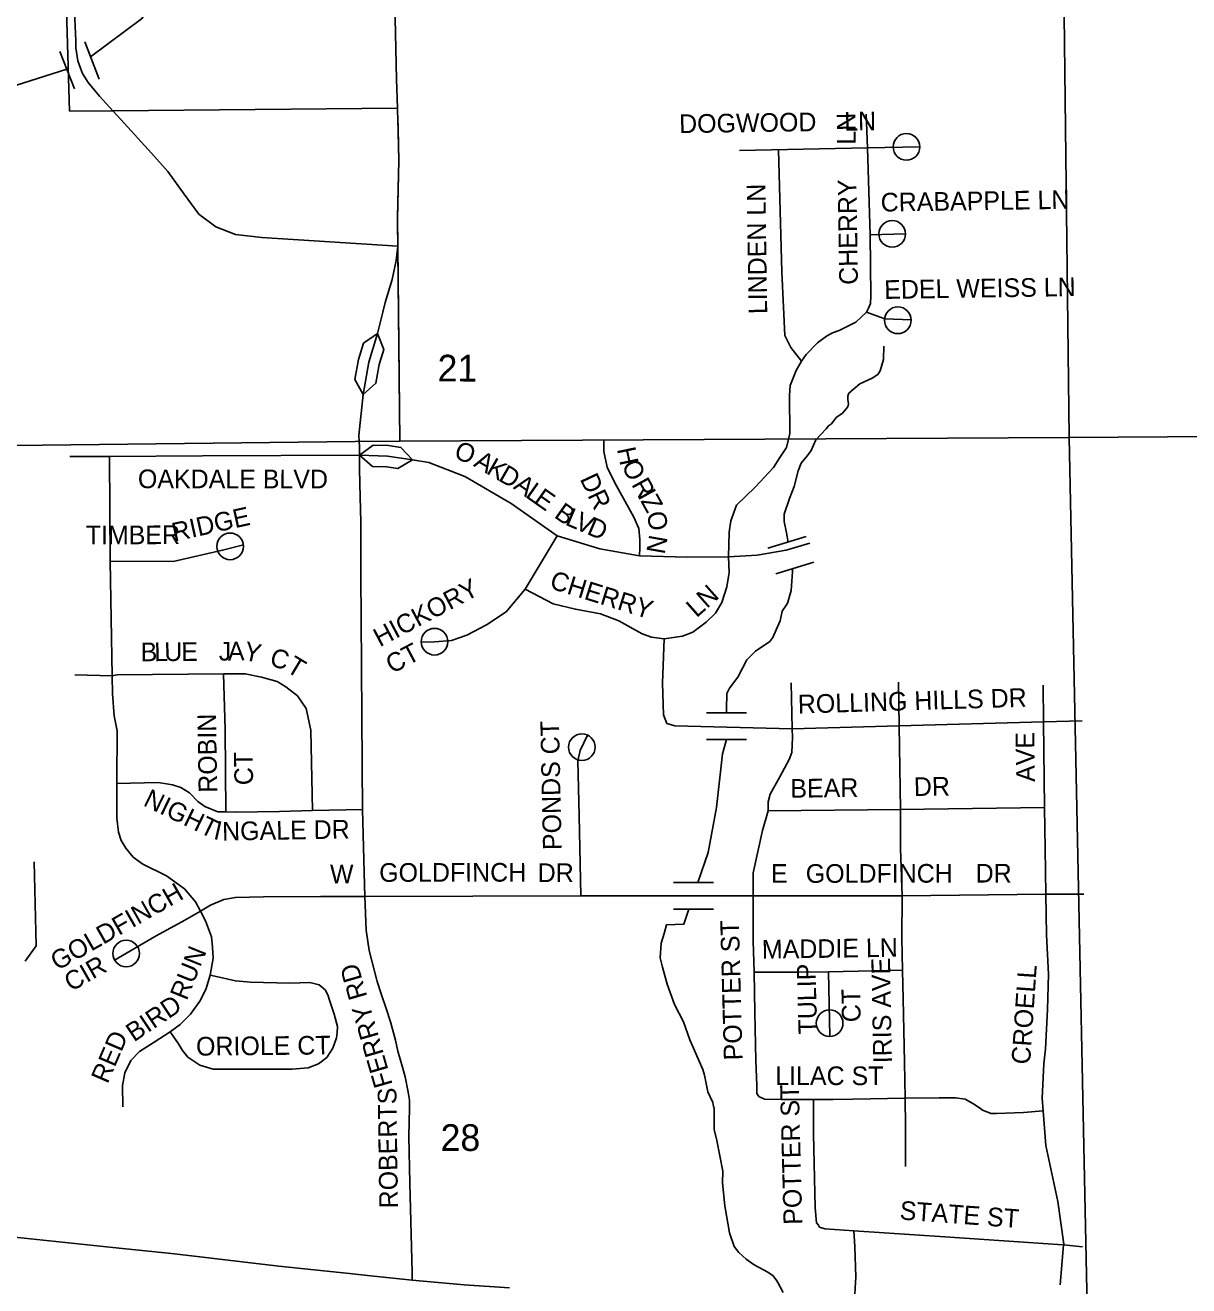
# Model space of a CAD drawing. Extents: x 281.94 to 289.14, y 116.09 to 120.89.
# Drawn here: x 283.875 to 284.748, y 118.797 to 119.742 of the extents above; entities that cross this region are included whole.
import ezdxf

# ---------------------------------------------------------------- set-up
doc = ezdxf.new("R2010")
doc.units = 0
for name, color, linetype in [('tdCiCityCuldesac', 7, 'Continuous'), ('tdCiCityDivCarto', 7, 'Continuous'), ('tdCiCityDivCL', 7, 'Continuous'), ('tdCiCityStreetCL', 7, 'Continuous'), ('tdCiCityStreetTxt', 7, 'Continuous'), ('tdCiCorpBndry', 7, 'Continuous'), ('tdCiCorpBndryPart', 7, 'Continuous'), ('tdCiHydroRiver', 7, 'Continuous'), ('tdCiPriCL', 7, 'Continuous'), ('tdCiPriDiv', 7, 'Continuous'), ('tdCiSecCL', 7, 'Continuous'), ('tdCiSecDivCL', 7, 'Continuous'), ('tdCiSectLine', 7, 'Continuous'), ('tdCiSectNmbr', 7, 'Continuous'), ('tdCiStrucCartoClvrt', 7, 'Continuous')]:
    doc.layers.add(name, color=color, linetype=linetype)

msp = doc.modelspace()

# ---------------------------------------------------------------- linework, layer by layer
at = {"layer": 'tdCiCityCuldesac'}
for centre in [(284.53592, 119.65052), (284.52524, 119.58531), (284.52947, 119.52057), (284.0288, 119.35111), (284.18207, 119.27963), (284.29256, 119.20057), (283.95083, 119.04592), (284.47832, 118.99364)]:
    msp.add_circle(centre, 0.01, dxfattribs=at)
at = {"layer": 'tdCiCityDivCarto'}
for points in [[(284.12858, 119.46491), (284.12241, 119.47613), (284.125, 119.49112), (284.12872, 119.50332), (284.13929, 119.51055)], [(284.12858, 119.46491), (284.13817, 119.4734), (284.14059, 119.48741), (284.14402, 119.49865), (284.13929, 119.51055)], [(284.12583, 119.41946), (284.13613, 119.42707), (284.14765, 119.42662), (284.1569, 119.42524), (284.16561, 119.41585)], [(284.12583, 119.41946), (284.13551, 119.41108), (284.14615, 119.41066), (284.15453, 119.40941), (284.16561, 119.41585)]]:
    msp.add_lwpolyline(points, dxfattribs=at)
at = {"layer": 'tdCiCityDivCL'}
msp.add_lwpolyline([(284.12583, 119.41946), (284.1469, 119.41864), (284.16561, 119.41585)], dxfattribs=at)
at = {"layer": 'tdCiCityStreetCL'}
for points in [[(283.94075, 119.67764), (283.93095, 119.68864), (283.92232, 119.69875), (283.91813, 119.70566), (283.91665, 119.70966), (283.91468, 119.71503), (283.9132, 119.72489), (283.91302, 119.73017), (283.91246, 119.74659), (283.91147, 119.79764), (283.90777, 119.92254), (283.90746, 119.9292)], [(284.15422, 119.67956), (284.15367, 119.70128), (284.14994, 119.86124), (284.14973, 119.90648), (284.14972, 119.9085), (284.14966, 119.9217), (284.14959, 119.9302)], [(284.50681, 119.64974), (284.50583, 119.6752)], [(284.41072, 119.64782), (284.50681, 119.64974)], [(284.45714, 119.48991), (284.44921, 119.50029), (284.44482, 119.50907), (284.44253, 119.5569), (284.4401, 119.64826)], [(284.50681, 119.64974), (284.54592, 119.65052)], [(284.50881, 119.58468), (284.50681, 119.64974)], [(284.50592, 119.52671), (284.50592, 119.52671), (284.50748, 119.52953), (284.50888, 119.53308), (284.50922, 119.53889), (284.50881, 119.58468)], [(284.50881, 119.58468), (284.53524, 119.58549)], [(284.45714, 119.48991), (284.46069, 119.49498), (284.46931, 119.50362), (284.47603, 119.50863), (284.48053, 119.51107), (284.48547, 119.51303), (284.49799, 119.51911), (284.50592, 119.52671)], [(284.53946, 119.52097), (284.51977, 119.52164), (284.50592, 119.52671)], [(284.40246, 119.34319), (284.403, 119.36171), (284.40417, 119.3703), (284.40847, 119.38202), (284.42237, 119.39556), (284.43621, 119.41024), (284.44087, 119.41763), (284.446, 119.42526), (284.44853, 119.43573), (284.4482, 119.46426), (284.4487, 119.47168), (284.45326, 119.48299), (284.45714, 119.48991)], [(284.12583, 119.41946), (284.12583, 119.42009), (284.12587, 119.42588), (284.12552, 119.4297)], [(284.33578, 119.34403), (284.33606, 119.34989), (284.33606, 119.3563), (284.33522, 119.36439), (284.33159, 119.37292), (284.31732, 119.39883), (284.31141, 119.41042), (284.30895, 119.42221), (284.30911, 119.43014)], [(283.9085, 119.41837), (283.9384, 119.41852)], [(283.9384, 119.41852), (284.00803, 119.41887), (284.12583, 119.41946)], [(283.93875, 119.33998), (283.9384, 119.41852)], [(284.12772, 119.18661), (284.12775, 119.18729), (284.12701, 119.29728), (284.12688, 119.32801), (284.12671, 119.36923), (284.12611, 119.39789), (284.12577, 119.40973), (284.12583, 119.41946)], [(284.16561, 119.41585), (284.17783, 119.41402), (284.20353, 119.40385), (284.20525, 119.40317), (284.23947, 119.38334), (284.27403, 119.35896)], [(284.25009, 119.31906), (284.27403, 119.35896)], [(284.27403, 119.35896), (284.30593, 119.34933), (284.33578, 119.34403)], [(283.93875, 119.33998), (283.98607, 119.33975), (284.02316, 119.34817), (284.03873, 119.35225)], [(284.40246, 119.34319), (284.42394, 119.34459), (284.4457, 119.34821), (284.46355, 119.35351)], [(283.94023, 119.25405), (283.93875, 119.33998)], [(284.33578, 119.34403), (284.37149, 119.34291), (284.40246, 119.34319)], [(284.35432, 119.2817), (284.36788, 119.28367), (284.37577, 119.28687), (284.38563, 119.29427), (284.39279, 119.30093), (284.39752, 119.30897), (284.40115, 119.32067), (284.40302, 119.33143), (284.40246, 119.34319)], [(284.17207, 119.27923), (284.18214, 119.27963), (284.19485, 119.28052), (284.20635, 119.28441), (284.22109, 119.29221), (284.2357, 119.30192), (284.25009, 119.31906)], [(284.25009, 119.31906), (284.27096, 119.30808), (284.28773, 119.30389), (284.30647, 119.30044), (284.32028, 119.29526), (284.33779, 119.28564), (284.34488, 119.28312), (284.35432, 119.2817)], [(284.35432, 119.2817), (284.35308, 119.24865), (284.35382, 119.22473), (284.35629, 119.21832), (284.36221, 119.21659), (284.45033, 119.21429)], [(283.94023, 119.25405), (283.91246, 119.25478)], [(284.02381, 119.25544), (283.94419, 119.25478), (283.94023, 119.25405)], [(283.94394, 119.17332), (283.94395, 119.17482), (283.94413, 119.21279), (283.9418, 119.22417), (283.94058, 119.24067), (283.94023, 119.25405)], [(284.0892, 119.21343), (284.08585, 119.22955), (284.07925, 119.23911), (284.07062, 119.24572), (284.06396, 119.24971), (284.05231, 119.25301), (284.04015, 119.25562), (284.02381, 119.25544)], [(284.02501, 119.21376), (284.02381, 119.25544)], [(284.45033, 119.21429), (284.44949, 119.24879)], [(284.53041, 119.2166), (284.52988, 119.24929)], [(284.63876, 119.21947), (284.63846, 119.2471)], [(284.45033, 119.21429), (284.53041, 119.2166)], [(284.53041, 119.2166), (284.63876, 119.21947)], [(284.53141, 119.15375), (284.53041, 119.2166)], [(284.63876, 119.21947), (284.66762, 119.22024)], [(284.63946, 119.15533), (284.63876, 119.21947)], [(284.02564, 119.15199), (284.02501, 119.21375)], [(284.0905, 119.15297), (284.0892, 119.21343)], [(284.29172, 119.08909), (284.29043, 119.14925), (284.28947, 119.19033), (284.29139, 119.19803), (284.29675, 119.20964)], [(284.43212, 119.15286), (284.43229, 119.1595), (284.43372, 119.1653), (284.44087, 119.17837), (284.44807, 119.19132), (284.44999, 119.19657), (284.45049, 119.20772), (284.45033, 119.21429)], [(284.12798, 119.15375), (284.12772, 119.18661)], [(284.00646, 119.07771), (284.00287, 119.08474), (283.99452, 119.09436), (283.98104, 119.10399), (283.96339, 119.11298), (283.95601, 119.11811), (283.95055, 119.12485), (283.94702, 119.13063), (283.9451, 119.13673), (283.94381, 119.14732), (283.94388, 119.16121), (283.94394, 119.17332)], [(283.94394, 119.17332), (283.97494, 119.17396), (283.98113, 119.17302), (283.98554, 119.17235), (283.99195, 119.17043), (283.99837, 119.16626), (284.00447, 119.15984), (284.00993, 119.15599), (284.01956, 119.15213), (284.02564, 119.15199)], [(284.02564, 119.15199), (284.03271, 119.15181), (284.06577, 119.15246), (284.0905, 119.15297)], [(284.0905, 119.15297), (284.12798, 119.15375)], [(284.12979, 119.08864), (284.12947, 119.09728), (284.12798, 119.15375)], [(284.42788, 119.13806), (284.43212, 119.15286)], [(284.43212, 119.15286), (284.53141, 119.15375)], [(284.53141, 119.15375), (284.63946, 119.15533)], [(284.53264, 119.08916), (284.53141, 119.12455), (284.53141, 119.15375)], [(284.64043, 119.09038), (284.63994, 119.12428), (284.63946, 119.15533)], [(284.42108, 119.08916), (284.421, 119.10643), (284.42788, 119.13806)], [(283.87514, 119.04026), (283.87516, 119.04027), (283.8833, 119.05161), (283.88197, 119.11457)], [(284.12979, 119.08864), (284.09658, 119.08859), (284.0539, 119.08827), (284.03271, 119.08795), (284.02405, 119.08634), (284.0141, 119.08217), (284.00646, 119.07771)], [(284.12979, 119.08864), (284.29172, 119.08909)], [(284.16541, 118.8009), (284.16537, 118.80679), (284.16365, 118.87362), (284.16276, 118.90862), (284.16326, 118.93032), (284.16321, 118.93599), (284.16227, 118.94192), (284.16005, 118.95351), (284.15801, 118.96067), (284.15455, 118.97279), (284.15282, 118.98102), (284.14895, 118.99469), (284.14569, 119.00473), (284.142, 119.01565), (284.13909, 119.02502), (284.13317, 119.0482), (284.1307, 119.06349), (284.12979, 119.08864)], [(284.29172, 119.08909), (284.29306, 119.08909), (284.34306, 119.08923), (284.42108, 119.08916)], [(284.42162, 119.03178), (284.42105, 119.05521), (284.42108, 119.08916)], [(284.42108, 119.08916), (284.53264, 119.08916)], [(284.53293, 119.0334), (284.53242, 119.05746), (284.53264, 119.08916)], [(284.53264, 119.08916), (284.64043, 119.09038)], [(284.63837, 118.92795), (284.63772, 118.93757), (284.63887, 118.96329), (284.64015, 118.97446), (284.64174, 119.00381), (284.64238, 119.03028), (284.64092, 119.05992), (284.64043, 119.09038)], [(284.64043, 119.09038), (284.66888, 119.09049)], [(284.00646, 119.07771), (283.99484, 119.07094), (283.97334, 119.05906), (283.94219, 119.04087)], [(284.01374, 119.02973), (284.01603, 119.04237), (284.0157, 119.05072), (284.01474, 119.05842), (284.01025, 119.07029), (284.00646, 119.07771)], [(283.9838, 118.98723), (283.99131, 118.99263), (283.99902, 119.00033), (284.00608, 119.01028), (284.01057, 119.01894), (284.01374, 119.02973)], [(283.9838, 118.98723), (283.99003, 118.97818), (283.99309, 118.97323), (283.99709, 118.96824), (284.00608, 118.96214), (284.01603, 118.95925), (284.03817, 118.95925), (284.0754, 118.95925), (284.08727, 118.96021), (284.09498, 118.9631), (284.10127, 118.96782), (284.10589, 118.97497), (284.10846, 118.98268), (284.1091, 118.98636), (284.10937, 118.99116), (284.10685, 119.00033), (284.103, 119.01156), (284.10242, 119.0141), (284.10043, 119.0183), (284.09562, 119.02247), (284.08856, 119.02408), (284.07347, 119.02376), (284.04395, 119.0244), (284.03271, 119.02536), (284.02191, 119.02785), (284.01374, 119.02973)], [(284.42162, 119.03178), (284.45379, 119.03178), (284.47753, 119.03227)], [(284.42162, 119.03178), (284.42234, 119.00161), (284.42298, 118.96567), (284.42362, 118.94705), (284.42362, 118.94332), (284.42362, 118.94096), (284.42522, 118.93871), (284.4294, 118.93678), (284.44223, 118.93646), (284.46631, 118.93646)], [(284.47753, 119.03227), (284.53293, 119.0334)], [(284.4785, 118.98364), (284.47753, 119.03227)], [(284.53489, 118.93734), (284.53434, 118.96438), (284.53338, 119.01188), (284.53293, 119.0334)], [(283.94831, 118.93101), (283.94799, 118.94705), (283.94991, 118.95636), (283.9544, 118.96567), (283.96082, 118.97241), (283.97174, 118.97947), (283.9838, 118.98723)], [(284.46631, 118.93646), (284.48075, 118.93646), (284.49541, 118.9366), (284.53489, 118.93734)], [(284.46631, 118.93646), (284.46631, 118.91079), (284.46759, 118.85526), (284.46855, 118.84403), (284.46987, 118.84214), (284.4708, 118.84082), (284.47465, 118.83954), (284.49648, 118.83806)], [(284.53489, 118.93734), (284.56034, 118.93775), (284.57271, 118.93763), (284.57991, 118.93659), (284.5857, 118.93349), (284.59059, 118.9301), (284.59304, 118.9284), (284.59936, 118.92606), (284.60347, 118.92603), (284.62378, 118.92665), (284.63837, 118.92795)], [(284.53533, 118.88611), (284.53531, 118.91624), (284.53489, 118.93734)], [(284.6538, 118.82739), (284.65386, 118.82803), (284.64939, 118.85993), (284.64046, 118.90204), (284.63837, 118.92795)], [(284.49987, 118.66137), (284.49908, 118.66387), (284.4984, 118.67089), (284.49741, 118.68446), (284.49509, 118.72961), (284.49514, 118.74362), (284.49459, 118.75303), (284.49583, 118.77375), (284.49629, 118.77896), (284.49731, 118.79027), (284.49758, 118.79521), (284.49805, 118.80334), (284.49731, 118.82628), (284.49648, 118.83806)], [(284.49648, 118.83806), (284.56483, 118.83344), (284.65323, 118.82745), (284.6538, 118.82739)], [(284.65121, 118.79763), (284.6538, 118.82739)], [(284.6538, 118.82739), (284.66789, 118.82606)]]:
    msp.add_lwpolyline(points, dxfattribs=at)
at = {"layer": 'tdCiCorpBndry'}
msp.add_lwpolyline([(283.90096, 119.92932), (283.90847, 119.67735), (283.94087, 119.67764), (284.15422, 119.67956), (284.15429, 119.6768), (284.15453, 119.67179), (284.15522, 119.64041), (284.15429, 119.59631), (284.15595, 119.43005), (284.1225, 119.42966), (283.2912, 119.42007), (283.29586, 118.89344), (283.2751, 118.89569), (283.20343, 118.90239), (283.17567, 118.90564), (283.16064, 118.90695), (283.14216, 118.90855), (283.12665, 118.91148), (283.11496, 118.91327), (283.09906, 118.91855), (283.07551, 118.92788), (283.05148, 118.93762), (283.01972, 118.95139), (283.01903, 118.48418)], dxfattribs=at)
at = {"layer": 'tdCiCorpBndryPart'}
for points in [[(285.15827, 119.93339), (285.15814, 119.93902), (284.9038, 119.93593), (284.90133, 120.18454), (284.39843, 120.18142), (284.40027, 119.93372), (284.14959, 119.9302), (283.90743, 119.92938), (283.90096, 119.92932), (283.90847, 119.67735), (283.94087, 119.67764), (284.15422, 119.67956)], [(284.15449, 119.5761), (284.15595, 119.43005), (284.1225, 119.42966), (283.2912, 119.42007), (283.29586, 118.89344), (283.29586, 118.89344)]]:
    msp.add_lwpolyline(points, dxfattribs=at)
at = {"layer": 'tdCiHydroRiver'}
for points in [[(283.92419, 119.71796), (283.96237, 119.74645), (284.01602, 119.80993), (284.088, 119.8662), (284.13975, 119.90115)], [(283.86225, 119.69476), (283.90633, 119.70873)], [(284.51901, 119.50108), (284.51877, 119.49105), (284.51628, 119.48274), (284.51437, 119.48001), (284.51023, 119.47724), (284.50091, 119.47303), (284.49284, 119.46584), (284.49194, 119.46365), (284.49205, 119.46128), (284.49238, 119.45787), (284.49188, 119.4558), (284.48805, 119.45097), (284.4831, 119.44767), (284.47978, 119.44305), (284.47756, 119.44146), (284.47564, 119.43915), (284.46788, 119.43103), (284.46458, 119.42291), (284.46166, 119.41924), (284.45702, 119.41336), (284.45462, 119.40783), (284.45175, 119.396), (284.44825, 119.38705), (284.44416, 119.37529), (284.4443, 119.36961), (284.44607, 119.36128), (284.44721, 119.35426)], [(284.45058, 119.33438), (284.45052, 119.33204), (284.44948, 119.31807), (284.447, 119.30924), (284.4466, 119.308), (284.44278, 119.30255), (284.4412, 119.29518), (284.4383, 119.28861), (284.43579, 119.28278), (284.43338, 119.27984), (284.42286, 119.2726), (284.41943, 119.26933), (284.41631, 119.26596), (284.40948, 119.25311), (284.40314, 119.24482), (284.40134, 119.24076), (284.4009, 119.22898), (284.40109, 119.22629)], [(284.40096, 119.20629), (284.39788, 119.19549), (284.39359, 119.15527), (284.38715, 119.12149), (284.37957, 119.0992)], [(284.37277, 119.0792), (284.36892, 119.06788), (284.35601, 119.06744), (284.35422, 119.061), (284.35203, 119.05362), (284.35129, 119.04276), (284.35296, 119.03557), (284.35649, 119.02283), (284.36206, 119.00756), (284.36874, 118.99457), (284.37359, 118.98114), (284.38337, 118.95893), (284.38441, 118.95471), (284.38692, 118.94227), (284.39083, 118.93429), (284.39136, 118.9312), (284.39167, 118.93018), (284.39166, 118.91406), (284.39375, 118.90564), (284.39815, 118.88269), (284.3981, 118.87391), (284.39983, 118.8567), (284.4032, 118.83662), (284.40682, 118.82616), (284.4103, 118.82169), (284.41571, 118.81674), (284.42182, 118.81253), (284.43211, 118.80705), (284.43588, 118.80414), (284.43865, 118.80058), (284.43946, 118.79935), (284.44351, 118.79187)]]:
    msp.add_lwpolyline(points, dxfattribs=at)
at = {"layer": 'tdCiPriCL'}
msp.add_lwpolyline([(283.86496, 118.8334), (283.94077, 118.82561), (283.98704, 118.82074), (284.06538, 118.81156), (284.11837, 118.80596), (284.13169, 118.80458), (284.16541, 118.8009), (284.20425, 118.79752), (284.23834, 118.79525)], dxfattribs=at)
at = {"layer": 'tdCiPriDiv'}
msp.add_lwpolyline([(283.86496, 118.8334), (283.94077, 118.82561), (283.98704, 118.82074), (284.06538, 118.81156), (284.11837, 118.80596), (284.13169, 118.80458), (284.16541, 118.8009), (284.20425, 118.79752), (284.23834, 118.79525)], dxfattribs=at)
at = {"layer": 'tdCiSecCL'}
for points in [[(284.15449, 119.5761), (284.15432, 119.59779), (284.15522, 119.64041), (284.1547, 119.66406), (284.15453, 119.67179), (284.15429, 119.6768), (284.15422, 119.67956)], [(284.15449, 119.5761), (284.05245, 119.58259), (284.03272, 119.58493), (284.01818, 119.59064), (284.00539, 119.60001), (283.99433, 119.61515), (283.982, 119.63217), (283.96992, 119.64573), (283.94674, 119.67113), (283.94075, 119.67764)], [(284.13929, 119.51055), (284.14318, 119.52665), (284.145, 119.53392), (284.15019, 119.55105), (284.1533, 119.56533), (284.15449, 119.5761)], [(284.12552, 119.4297), (284.12527, 119.43423), (284.12858, 119.46491)]]:
    msp.add_lwpolyline(points, dxfattribs=at)
at = {"layer": 'tdCiSecDivCL'}
msp.add_lwpolyline([(284.12858, 119.46491), (284.1328, 119.48927), (284.13929, 119.51055)], dxfattribs=at)
at = {"layer": 'tdCiSectLine'}
for points in [[(284.70051, 117.62466), (284.6788, 118.43087), (284.65788, 119.43258), (284.64838, 120.23497)], [(284.15595, 119.43005), (284.65788, 119.43258), (285.02609, 119.43521)]]:
    msp.add_lwpolyline(points, dxfattribs=at)
at = {"layer": 'tdCiStrucCartoClvrt'}
for p, q in [((283.91973, 119.72937), (283.93066, 119.70143)), ((283.9011, 119.72208), (283.91204, 119.69414)), ((284.43205, 119.34963), (284.46074, 119.3584)), ((284.4379, 119.3305), (284.46659, 119.33928)), ((284.38601, 119.22629), (284.41601, 119.22629)), ((284.38601, 119.20629), (284.41601, 119.20629)), ((284.36118, 119.09921), (284.39118, 119.09919)), ((284.36116, 119.07921), (284.39116, 119.07919))]:
    msp.add_line(p, q, dxfattribs=at)

# ---------------------------------------------------------------- texts
at = {"layer": 'tdCiCityStreetTxt'}
for s, rotation, p in [('DOGWOOD    LN', 0.85626, (284.36556, 119.66083)), ('CHERRY     LN', 90.85626, (284.49955, 119.54723)), ('LINDEN LN', 90.85626, (284.43156, 119.52526)), ('CRABAPPLE LN', 0.85626, (284.51671, 119.60202)), ('EDEL WEISS LN', 0.85626, (284.51933, 119.53656)), ('O', 338.41118, (284.19583, 119.41765)), ('H', 281.79319, (284.31877, 119.42406)), ('A', 329.91111, (284.21066, 119.41159)), ('K', 329.91111, (284.22013, 119.4061)), ('O', 297.05057, (284.32195, 119.41176)), ('OAKDALE BLVD', 359.94079, (283.95964, 119.39471)), ('D', 329.91111, (284.22924, 119.40083)), ('DR', 295.11833, (284.29083, 119.40167)), ('A', 324.7905, (284.24054, 119.39483)), ('L', 324.7905, (284.24948, 119.38852)), ('R', 298.82785, (284.32943, 119.39758)), ('E', 324.7905, (284.25567, 119.38415)), ('I', 298.82785, (284.33409, 119.38911)), ('Z', 298.82785, (284.33624, 119.3852)), ('RIDGE', 12.47803, (283.98679, 119.35455)), ('B', 324.7905, (284.27103, 119.37331)), ('L', 336.79622, (284.27936, 119.36755)), ('V', 336.79622, (284.28632, 119.36457)), ('O', 279.96828, (284.34116, 119.3762)), ('D', 336.79622, (284.2956, 119.36059)), ('TIMBER', 0.21676, (283.92056, 119.35254)), ('N', 259.95041, (284.34316, 119.36041)), ('CHERRY', 342.71208, (284.26765, 119.31985)), ('HICKORY', 27.90346, (284.14102, 119.27535)), ('LN', 41.56, (284.37849, 119.29714)), ('B', 0.47518, (283.96175, 119.26493)), ('L', 0.47518, (283.97189, 119.26501)), ('U', 0.47518, (283.97947, 119.26508)), ('E', 0.47518, (283.99215, 119.26518)), ('J', 0.60984, (284.02034, 119.26541)), ('A', 0.60984, (284.02717, 119.26548)), ('Y', 347.90482, (284.03818, 119.26627)), ('C', 344.16792, (284.05771, 119.26187)), ('CT', 27.90346, (284.15025, 119.25532)), ('T', 329.10594, (284.07007, 119.25771)), ('ROLLING HILLS DR', 1.71551, (284.45468, 119.22573)), ('ROBIN ', 90.97356, (284.01916, 119.16651)), ('PONDS CT', 91.17411, (284.27738, 119.12358)), ('AVE', 90.85626, (284.63229, 119.17459)), (' CT', 90.97356, (284.04615, 119.16697)), ('BEAR        DR', 0.841, (284.44896, 119.16259)), ('NIGHT', 334.20733, (283.96292, 119.15714)), ('I', 347.05345, (284.01569, 119.13195)), ('NGALE DR', 0.97468, (284.02289, 119.13051)), ('GOLDFINCH', 0.08691, (284.14057, 119.09962)), ('GOLDFINCH', 0.08691, (284.46043, 119.09885)), ('GOLDFINCH ', 29.72554, (283.89928, 119.03276)), ('POTTER ST', 91.51857, (284.41307, 118.96597)), ('MADDIE LN', 0.841, (284.42759, 119.04196)), ('RUN', 67.95419, (283.9962, 119.01007)), ('CIR', 29.72554, (283.90952, 119.01701)), ('FERRY RD', 106.10645, (284.15082, 118.94762)), ('TULIP', 91.52857, (284.46904, 118.98543)), ('IRIS AVE', 91.09211, (284.52508, 118.96377)), ('CROELL', 86.10334, (284.62858, 118.96241)), ('CT', 91.03863, (284.5016, 118.99449)), ('BIRD', 33.8314, (283.95668, 118.97922)), ('RED', 66.71464, (283.9369, 118.94767)), ('ORIOLE CT', 0.52774, (284.00329, 118.96931)), ('LILAC ST', 359.90808, (284.43752, 118.94732)), ('ROBERTS', 90.80642, (284.15469, 118.85493)), ('POTTER ST', 91.44545, (284.45782, 118.84272)), ('STATE ST', 355.87126, (284.53053, 118.84653))]:
    msp.add_text(s, height=0.014, rotation=rotation, dxfattribs=at).set_placement(p)
for s, p in [('W', (284.10365, 119.09859)), ('DR', (284.25945, 119.09945)), ('E', (284.43432, 119.0989)), ('DR', (284.58779, 119.0991))]:
    msp.add_text(s, height=0.014, dxfattribs=at).set_placement(p)
at = {"layer": 'tdCiSectNmbr'}
for s, p in [('21', (284.18431, 119.47472)), ('28', (284.18659, 118.89793))]:
    msp.add_text(s, height=0.02, rotation=359.87748, dxfattribs=at).set_placement(p)

doc.saveas('drawing.dxf')
